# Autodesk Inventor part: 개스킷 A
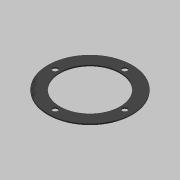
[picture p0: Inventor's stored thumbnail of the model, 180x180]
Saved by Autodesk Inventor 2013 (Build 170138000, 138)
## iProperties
Created: 2019-02
Part Number: 개스킷 A
Material: 고무
Document SubType Name: Modeling
Designer: mduedu
Density: 1 g/cm^3
Author: mduedu
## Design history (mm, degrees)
sketch "스케치1"
  geometry: C1 r 35 at (0, 0); C2 r 25 at (0, 0); 1 further point
  constraints: 2 centre point, 2 coincident
  dimensions: "d0" = 70 diameter of C1; "d1" = 50 diameter of C2
extrude "돌출1" new body sketch "스케치1" distance "d2" = 1; taper "d3" = 0 deg
sketch "스케치2" dims "d4" = 58
  geometry: 3 further points
  constraints: 2 vertical alignment, 1 coincident, 2 other
hole "구멍1" sketch "스케치2" at (0, 29) diameter "d5" = 4.5; stored, may be unused: countersink angle "d9" = 90 deg, drill point angle "d11" = 118 deg; dims "d6" = 6, "d7" = 4, "d8" = 2, "d10" = 8
node "솔리드1"
pattern_circular "원형 패턴1" dims angle "d13" = 360 deg
